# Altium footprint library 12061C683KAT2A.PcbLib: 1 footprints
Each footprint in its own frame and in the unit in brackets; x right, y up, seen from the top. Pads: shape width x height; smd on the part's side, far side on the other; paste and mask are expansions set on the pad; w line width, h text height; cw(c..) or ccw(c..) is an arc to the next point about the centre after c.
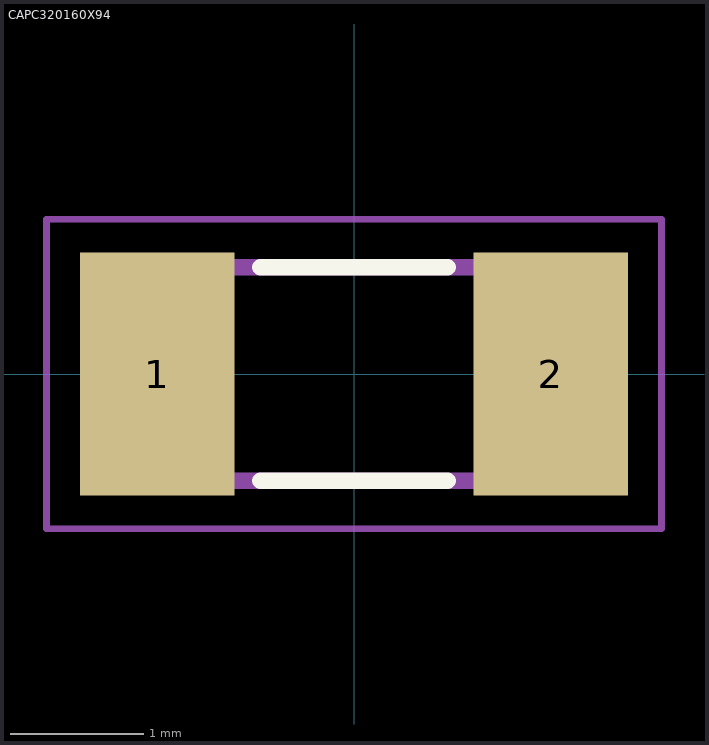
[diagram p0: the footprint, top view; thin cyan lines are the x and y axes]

## CAPC320160X94 [mm]
pads (2):
  rect 1.16x1.82 smd: 1(-1.475,0) 2(1.475,0)
Top Overlay:
  lines w0.127: -0.7,-0.8 0.7,-0.8 ; -0.7,0.8 0.7,0.8
Mechanical 4:
  lines w0.127: -1.6,-0.8 -1.6,0.8 ; -1.6,-0.8 1.6,-0.8 ; -1.6,-0.8 -1.6,0.8 ; -1.6,-0.8 1.6,-0.8 ; -1.6,0.8 1.6,0.8 ; -1.6,0.8 1.6,0.8 ; 1.6,-0.8 1.6,0.8 ; 1.6,-0.8 1.6,0.8
Mechanical 16:
  lines w0.05: -2.305,-1.16 -2.305,1.16 2.305,1.16 2.305,-1.16 -2.305,-1.16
